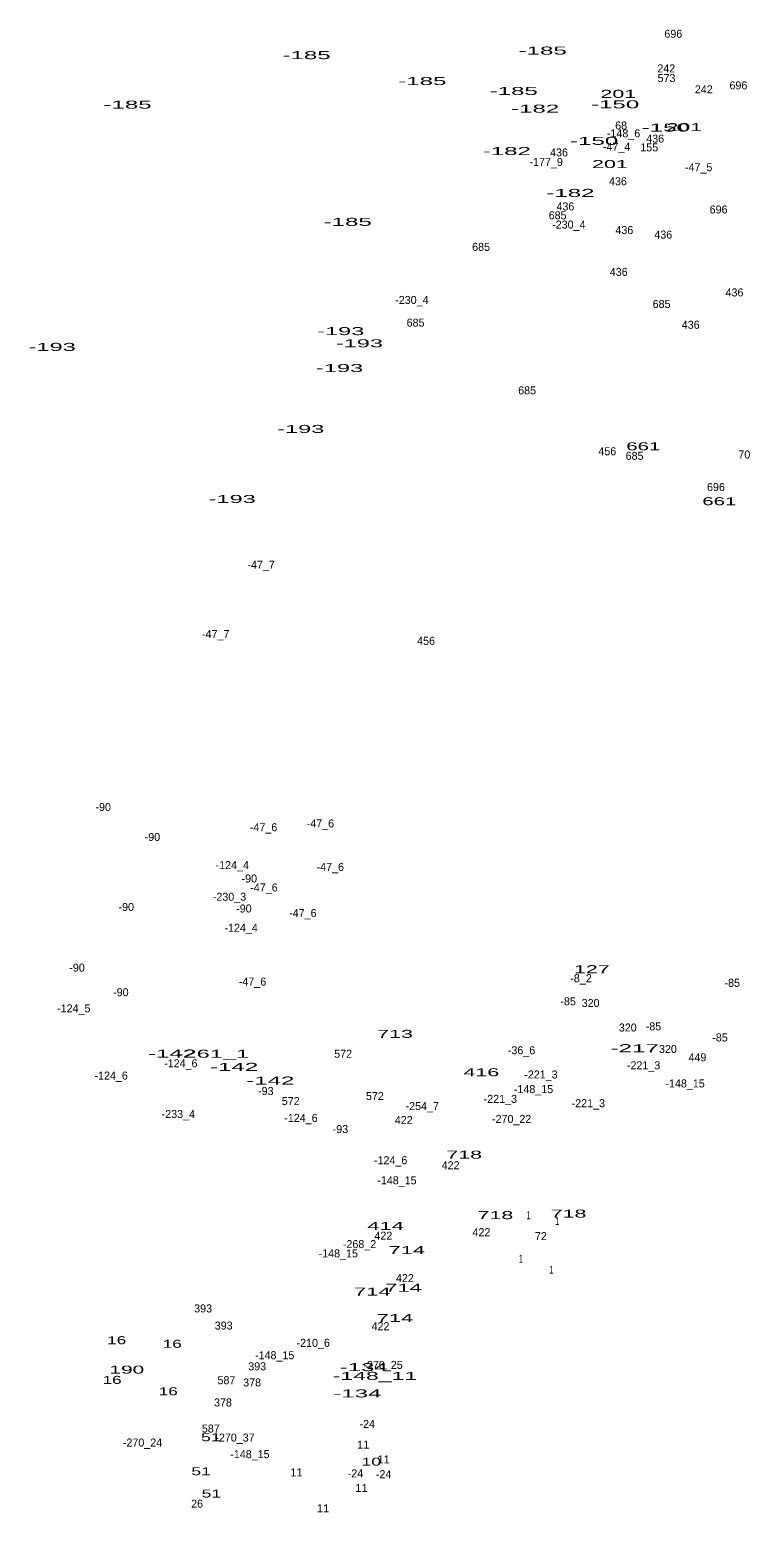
# Model space of a CAD drawing. Extents: x -658595 to -655205, y -1004347 to -1000147.
# Drawn here: x -657344 to -656989, y -1002981 to -1002240 of the extents above; entities that cross this region are included whole.
import ezdxf
from ezdxf.enums import TextEntityAlignment as Align

# ---------------------------------------------------------------- set-up
doc = ezdxf.new("R2010")
doc.units = 0
doc.header["$LTSCALE"] = 1.6
doc.layers.add('24', color=7, linetype='Continuous')

msp = doc.modelspace()

# ---------------------------------------------------------------- texts
at = {"layer": '24'}
for s, p in [('696', (-657022.503, -1002243.62)), ('242', (-657026.011, -1002260.92)), ('573', (-657025.913, -1002265.74)), ('242', (-657007.281, -1002271.39)), ('696', (-656990.003, -1002269.42)), ('-148_6', (-657047.356, -1002293.4)), ('68', (-657048.563, -1002289.47)), ('-47_4', (-657050.806, -1002300.05)), ('155', (-657034.52, -1002300.38)), ('436', (-657031.567, -1002296.02)), ('-177_9', (-657086.002, -1002307.69)), ('436', (-657079.587, -1002302.93)), ('-47_5', (-657009.852, -1002310.33)), ('436', (-657050.157, -1002317.35)), ('436', (-657076.397, -1002329.91)), ('685', (-657080.273, -1002334.35)), ('696', (-656999.893, -1002331.45)), ('-230_4', (-657074.681, -1002338.99)), ('436', (-657046.967, -1002341.75)), ('436', (-657027.527, -1002343.99)), ('685', (-657118.503, -1002350.14)), ('436', (-657049.777, -1002362.63)), ('436', (-656991.967, -1002372.91)), ('-230_4', (-657153.041, -1002376.66)), ('685', (-657028.353, -1002378.67)), ('685', (-657151.213, -1002388)), ('436', (-657013.837, -1002389.08)), ('685', (-657095.493, -1002421.86)), ('456', (-657055.457, -1002452.3)), ('685', (-657041.853, -1002454.58)), ('705', (-656985.557, -1002453.89)), ('696', (-657001.213, -1002470.19)), ('-47_7', (-657228.348, -1002509.02)), ('-47_7', (-657251.008, -1002543.69)), ('456', (-657145.977, -1002547.05)), ('-90', (-657307.194, -1002630.13)), ('-47_6', (-657227.088, -1002640.23)), ('-47_6', (-657198.728, -1002638.33)), ('-90', (-657282.624, -1002645.11)), ('-124_4', (-657242.745, -1002659.17)), ('-47_6', (-657193.778, -1002660.05)), ('-90', (-657234.234, -1002665.86)), ('-47_6', (-657226.908, -1002670.34)), ('-230_3', (-657244.126, -1002674.98)), ('-90', (-657295.674, -1002680.07)), ('-90', (-657236.924, -1002680.84)), ('-47_6', (-657207.488, -1002683.1)), ('-124_4', (-657238.325, -1002690.51)), ('-90', (-657320.254, -1002710.42)), ('-8_2', (-657068.603, -1002715.7)), ('-90', (-657298.364, -1002722.71)), ('-47_6', (-657232.618, -1002717.38)), ('-85', (-656993.085, -1002718)), ('-124_5', (-657321.88, -1002730.75)), ('-85', (-657075.025, -1002727.27)), ('320', (-657063.801, -1002728.05)), ('320', (-657045.261, -1002740.33)), ('-85', (-657032.405, -1002739.75)), ('-85', (-656999.185, -1002745.32)), ('572', (-657187.403, -1002753.45)), ('-36_6', (-657098.293, -1002751.71)), ('320', (-657025.201, -1002751.07)), ('-124_6', (-657268.426, -1002758.21)), ('-221_3', (-657037.356, -1002759.24)), ('449', (-657010.471, -1002755.24)), ('-124_6', (-657303.216, -1002764.36)), ('-221_3', (-657088.616, -1002763.81)), ('-148_15', (-657016.633, -1002768.29)), ('-93', (-657225.99, -1002772.09)), ('572', (-657171.523, -1002774.57)), ('-148_15', (-657092.323, -1002771.15)), ('572', (-657213.553, -1002777.14)), ('-254_7', (-657147.872, -1002779.59)), ('-221_3', (-657108.876, -1002775.99)), ('-221_3', (-657064.936, -1002778.17)), ('-233_4', (-657269.667, -1002783.57)), ('-124_6', (-657208.446, -1002785.52)), ('422', (-657157.121, -1002786.59)), ('-270_22', (-657103.231, -1002786.02)), ('-93', (-657188.74, -1002791.1)), ('-124_6', (-657163.656, -1002806.67)), ('422', (-657133.721, -1002809.18)), ('-148_15', (-657160.503, -1002816.72)), ('422', (-657118.321, -1002842.64)), ('-268_2', (-657179.178, -1002848.6)), ('422', (-657167.291, -1002844.39)), ('72', (-657088.623, -1002844.6)), ('-148_15', (-657189.793, -1002853.25)), ('422', (-657156.541, -1002865.57)), ('393', (-657257.303, -1002880.75)), ('393', (-657247.033, -1002889.32)), ('422', (-657168.721, -1002889.64)), ('-210_6', (-657202.326, -1002897.95)), ('-148_15', (-657221.553, -1002904.13)), ('-270_25', (-657167.441, -1002908.98)), ('587', (-657245.663, -1002916.62)), ('393', (-657230.293, -1002909.67)), ('378', (-657232.823, -1002917.76)), ('378', (-657247.373, -1002927.75)), ('-24', (-657175.329, -1002938.48)), ('587', (-657253.463, -1002940.78)), ('-270_37', (-657241.387, -1002945.3)), ('-270_24', (-657287.545, -1002947.78)), ('-148_15', (-657233.913, -1002953.59)), ('-24', (-657181.229, -1002963.21)), ('-24', (-657167.149, -1002963.6)), ('26', (-657260.313, -1002978.35))]:
    msp.add_text(s, height=4, dxfattribs=at).set_placement(p, align=Align.CENTER)
for s, width, p in [('-185', 2.25, (-657205.641, -1002254.31)), ('-185', 2.25, (-657087.731, -1002252.03)), ('-185', 2.25, (-657147.831, -1002267.25)), ('-185', 2.25, (-657295.031, -1002279.04)), ('-185', 2.25, (-657102.181, -1002272.2)), ('-150', 2.25, (-657051.577, -1002278.88)), ('201', 2, (-657049.964, -1002273.64)), ('-182', 2.25, (-657091.481, -1002281.03)), ('-150', 2.25, (-657026.287, -1002290.49)), ('201', 2, (-657017.054, -1002290.28)), ('-150', 2.25, (-657062.037, -1002297.14)), ('-182', 2.25, (-657105.651, -1002302.24)), ('201', 2, (-657054.144, -1002308.74)), ('-182', 2.25, (-657073.881, -1002323.17)), ('-185', 2.25, (-657185.101, -1002337.64)), ('-193', 2.2, (-657188.585, -1002392.24)), ('-193', 2.2, (-657332.645, -1002400.14)), ('-193', 2.2, (-657179.265, -1002398.33)), ('-193', 2.2, (-657189.155, -1002410.7)), ('-193', 2.2, (-657208.555, -1002441.14)), ('661', 1.9, (-657037.497, -1002449.81)), ('-193', 2.2, (-657242.785, -1002476.14)), ('661', 1.9, (-656999.537, -1002477.27)), ('127', 2, (-657063.203, -1002711.19)), ('713', 2, (-657161.443, -1002743.51)), ('-142', 2.25, (-657272.806, -1002753.34)), ('-261_1', 2.2, (-657252.663, -1002753.44)), ('-217', 2.25, (-657041.785, -1002750.67)), ('-142', 2.25, (-657241.806, -1002760)), ('-142', 2.25, (-657223.746, -1002766.85)), ('416', 2, (-657118.368, -1002762.7)), ('718', 2, (-657126.933, -1002803.87)), ('718', 2, (-657111.343, -1002834.12)), ('1', 0.65, (-657094.777, -1002834.15)), ('718', 2, (-657074.823, -1002833.36)), ('414', 2.05, (-657166.159, -1002839.49)), ('1', 0.65, (-657080.427, -1002837.01)), ('714', 2.05, (-657155.608, -1002851.59)), ('1', 0.65, (-657098.587, -1002855.94)), ('1', 0.65, (-657083.467, -1002861.36)), ('714', 2.05, (-657157.228, -1002870.42)), ('714', 2.05, (-657172.818, -1002872.33)), ('714', 2.05, (-657161.508, -1002885.55)), ('16', 1.6, (-657300.453, -1002896.63)), ('16', 1.6, (-657272.693, -1002898.44)), ('16', 1.6, (-657302.733, -1002916.46)), ('190', 1.95, (-657295.409, -1002911.34)), ('-148_11', 2.15, (-657171.489, -1002914.48)), ('-134', 2.25, (-657177.086, -1002910.1)), ('16', 1.6, (-657274.683, -1002922.17)), ('-134', 2.25, (-657180.266, -1002923.23)), ('51', 1.65, (-657253.427, -1002945.12)), ('11', 1.05, (-657177.334, -1002948.81)), ('10', 1.65, (-657173.314, -1002957.34)), ('11', 1.05, (-657167.164, -1002956.23)), ('51', 1.65, (-657258.277, -1002962.15)), ('11', 1.05, (-657210.714, -1002962.7)), ('51', 1.65, (-657253.137, -1002973.28)), ('11', 1.05, (-657178.194, -1002970.5)), ('11', 1.05, (-657197.404, -1002980.68))]:
    msp.add_text(s, height=4, dxfattribs=dict(at, width=width)).set_placement(p, align=Align.CENTER)

doc.saveas('drawing.dxf')
